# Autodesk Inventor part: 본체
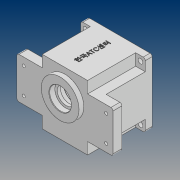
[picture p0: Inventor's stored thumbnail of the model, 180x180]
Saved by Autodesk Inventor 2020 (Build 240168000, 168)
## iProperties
Created: 2020-07
Part Number: 본체
Material: 일반
Document SubType Name: Modeling
Designer: PC312-
Density: 1 g/cm^3
Appearance: 기본값
Mass: 324.617 g
Surface Area: 793.597 cm^2
Volume: 324.617 cm^3
Author: PC312-
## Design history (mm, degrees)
sketch "스케치1"
  geometry: L1 (47, -47)-(-47, -47); L2 (-47, -47)-(-47, 47); L3 (-47, 47)-(47, 47); L4 (47, 47)-(47, -47); L5 (47, -47)-(-47, 47); L6 (-47, -47)-(47, 47); 1 further point
  constraints: 12 end point, 2 midpoint, 2 parallel, 1 horizontal, 1 perpendicular
  dimensions: "d0" = 94 distance of L2.end L3.end; "d1" = 94 distance of L1.end L2.end
extrude "돌출1" new body sketch "스케치1" distance "d2" = 80; taper "d3" = 0 deg
sketch "스케치2"
  geometry: L1 (70, -30)-(-70, -30); L2 (-70, -30)-(-70, 30); L3 (-70, 30)-(70, 30); L4 (70, 30)-(70, -30); L5 (70, -30)-(-70, 30); L6 (-70, -30)-(70, 30); 1 further point
  constraints: 12 end point, 2 midpoint, 2 parallel, 1 horizontal, 1 perpendicular
  dimensions: "d4" = 140 distance of L2.end L3.end; "d5" = 60 distance of L1.end L2.end
extrude "돌출2" join sketch "스케치2" distance "d6" = 13; taper "d7" = 0 deg
sketch "스케치3"
  geometry: L1 (33, 47)-(47, 47); L2 (47, 47)-(47, 30); L3 (47, 30)-(33, 30); L4 (33, 30)-(33, 47); L5 (47, 47)-(-47, 47) reference; L6 (47, -47)-(47, 47) reference; L7 (0, 0)-(0, -21.053); L8 (0, 0)-(-17.974, 0); L9 (-33, 30)-(-33, 47); L10 (-33, 47)-(-47, 47); L11 (-47, 47)-(-47, 30); L12 (-47, 30)-(-33, 30); L13 (-33, -30)-(-33, -47); L14 (-47, -30)-(-33, -30); L15 (-47, -47)-(-47, -30); L16 (33, -30)-(33, -47); L17 (33, -47)-(47, -47); L18 (47, -47)-(47, -30); L19 (47, -30)-(33, -30); L20 (-33, -47)-(-47, -47); 4 further points
  constraints: 36 end point, 12 symmetric about line, 2 collinear, 2 horizontal, 2 parallel, 1 perpendicular, 1 vertical
  dimensions: "d8" = 33 distance from line of L4 L7.start; "d9" = 30 distance from line of L3 L7.start
extrude "돌출3" cut sketch "스케치3" distance "d10" = 70; taper "d11" = 0 deg
sketch "스케치4"
  geometry: C1 r 27.5 at (0, 11); 1 further point
  constraints: 1 centre point, 1 vertical alignment
  dimensions: "d12" = 55 diameter of C1; "d13" = 11 distance of point (0, 0) C1.centre
extrude "돌출4" join sketch "스케치4" distance "d14" = 7; taper "d15" = 0 deg
sketch "스케치5"
  geometry: 2 further points
  constraints: 1 coincident
hole "구멍1" sketch "스케치5" at (0, 0) diameter "d16" = 80; stored, may be unused: countersink angle "d20" = 90 deg, drill point angle "d22" = 0 deg; dims "d17" = 4, "d18" = 86, "d19" = 9, "d21" = 71
sketch "스케치6"
  geometry: A1 r 21 centre (0, 11) between (8.978, -7.984) and (-8.978, -7.984); A2 r 15 centre (0, -20) between (-8.978, -7.984) and (8.978, -7.984); 1 further point
  constraints: 4 point on circle, 2 centre point, 2 vertical alignment
  dimensions: "d23" = 42 diameter of A1; "d24" = 30 diameter of A2; "d25" = 11 distance of point (0, 0) A1.centre; "d26" = 20 distance of point (0, 0) A2.centre
extrude "돌출5" join sketch "스케치6" distance "d27" = 7; taper "d28" = 0 deg
sketch "스케치7"
  geometry: A1 r 36 centre (0, 0) between (-36, 0) and (36, 0); A2 r 4 centre (-36, 0) between (-36.19, -3.995) and (-36.19, 3.995); A3 r 4 centre (36, 0) between (36.19, 3.995) and (36.19, -3.995); A4 r 40 centre (0, 0) between (-39.279, 7.559) and (-39.279, -7.559) reference; A5 r 3 centre (-36.333, 6.992) between (-39.279, 7.559) and (-35.772, 4.045); A6 r 3 centre (-36.333, -6.992) between (-35.772, -4.045) and (-39.279, -7.559); A7 r 3 centre (36.333, -6.992) between (39.279, -7.559) and (35.772, -4.045); A8 r 3 centre (36.333, 6.992) between (35.772, 4.045) and (39.279, 7.559); 1 further point
  constraints: 26 point on circle, 8 tangent, 7 centre point, 2 horizontal alignment, 1 coincident
  dimensions: "d29" = 72 diameter of A1; "d30" = 8 diameter of A2; "d31" = 8 diameter of A3; "d32" = 6 diameter of A5; "d33" = 6 diameter of A6; "d34" = 6 diameter of A7; "d35" = 6 diameter of A8
extrude "돌출6" join sketch "스케치7" stored distance "d36" = 7; taper "d37" = 0 deg
fillet "모깎기1" dims "d38" = 3
sketch "스케치8"
  geometry: C1 r 11 at (0, -20); A1 r 15 centre (0, -20) between (-11.584, -10.47) and (11.584, -10.47) reference; 1 further point
  constraints: 1 centre point, 1 coincident
  dimensions: "d39" = 22 diameter of C1
extrude "돌출7" cut sketch "스케치8" distance "d40" = 7; taper "d41" = 0 deg
sketch "스케치9"
  geometry: C1 r 11 at (0, 0) reference; C2 r 9.5 at (0, 0); 1 further point
  constraints: 1 centre point, 1 coincident
  dimensions: "d42" = 19 diameter of C2
extrude "돌출8" cut sketch "스케치9" distance "d43" = 3; taper "d44" = 0 deg
sketch "스케치10"
  geometry: A1 r 21 centre (0, 11) between (12.163, -6.119) and (-12.163, -6.119) reference; 2 further points
  constraints: 1 coincident
hole "구멍2" sketch "스케치10" at (0, 11) diameter "d45" = 25; stored, may be unused: countersink angle "d49" = 90 deg, drill point angle "d51" = 0 deg; dims "d46" = 4, "d47" = 35, "d48" = 10, "d50" = 71
sketch "스케치11"
  geometry: C1 r 12.5 at (0, 0) reference; C2 r 16 at (0, 0); 1 further point
  constraints: 1 centre point, 1 coincident
  dimensions: "d52" = 32 diameter of C2
extrude "돌출9" cut sketch "스케치11" distance "d53" = 8.3; taper "d54" = 0 deg
chamfer "모따기1" distance "d55" = 0.8; stored, may be unused: second distance "d56" = 2, angle "d57" = 30 deg
chamfer "모따기2" distance "d58" = 1; stored, may be unused: second distance "d59" = 2, angle "d60" = 30 deg
sketch "스케치13"
  geometry: A1 r 4 centre (-36, 0) between (-36.19, -3.995) and (-36.19, 3.995) reference; A2 r 4 centre (36, 0) between (36.19, 3.995) and (36.19, -3.995) reference; 3 further points
  constraints: 2 coincident
hole "구멍3" sketch "스케치13" at (-36, 0), (36, 0) diameter "d61" = 3.242; stored, may be unused: countersink angle "d65" = 90 deg, drill point angle "d67" = 118 deg; dims "d62" = 7, "d63" = 35, "d64" = 10, "d66" = 9
sketch "스케치14"
  geometry: L1 (-47, 47)-(-47, -47) reference; 2 further points
  dimensions: "d68" = 7 distance from line of L1 point (-40, 40); "d69" = 40 horizontal distance of point (0, 0) point (-40, 40)
hole "구멍4" sketch "스케치14" at (-40, 40) diameter "d70" = 7; stored, may be unused: countersink angle "d74" = 90 deg, drill point angle "d76" = 118 deg; dims "d71" = 7, "d72" = 35, "d73" = 10, "d75" = 9
sketch "스케치15"
  geometry: 3 further points
  constraints: 1 vertical alignment
  dimensions: "d83" = 38 distance of point (-60, -19) point (-60, 19); "d84" = 19 vertical distance of point (0, 0) point (-60, 19); "d85" = 60 horizontal distance of point (0, 0) point (-60, 19)
hole "구멍5" sketch "스케치15" at (-60, 19), (-60, -19) diameter "d86" = 4.5; stored, may be unused: countersink angle "d90" = 82 deg, drill point angle "d92" = 118 deg; dims "d87" = 7, "d88" = 10, "d89" = 5, "d91" = 9
fillet "모깎기2" dims "d93" = 3
fillet "모깎기3" dims "d94" = 3
node "작업 평면1"
sketch "스케치16"
  geometry: L1 (77, 80)-(-11, 80) reference; 2 further points
  constraints: 1 vertical alignment, 1 other
  dimensions: "d96" = 40 distance from line of L1 point (33, 40)
feature "엠보싱1" sketch "스케치16" dims "d0" = 94, "d1" = 94, "d97" = 0.5, "d98" = 0
node "솔리드1"
pattern_linear "직사각형 패턴1" dims "d79" = 80, "d82" = 80
mirror "미러1"
feature "A9D066F2-1C7D-4E18-AEED-F7BC21143FA4" dims "d16" = 80, "d17" = 4, "d18" = 86, "d19" = 9, "d20" = 90 deg, "d21" = 71, "d22" = 0
other parameters: "d95" = 17
